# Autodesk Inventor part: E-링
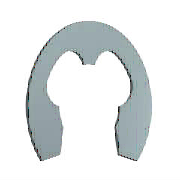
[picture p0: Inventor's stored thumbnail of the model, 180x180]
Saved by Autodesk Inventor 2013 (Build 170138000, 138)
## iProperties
IsCustomPart: 1
Created: 2012-02
Part Number: E-링
Material: 강철, 연강
Description: 일반용 테이퍼 및 줄어든 횡단면 리테이닝 링 - E-링 외부 시리즈 3CM1 리테이닝 링
Document SubType Name: Modeling
Standard: ANSI B27.7
Designer: mduedu
Standard Revision: 1999
Standards Organization: ANSI
Language: ko-KR
Size Designation: 5
Categories: <MemberInstance><Categories><Category DisplayName="샤프트 부품" InternalName="7f7aeb1f-a693-4053-b835-cee3144e0d98" Mnemonic="SHFT"><Category DisplayName="써클립" Inter
Density: 7.86 g/cm^3
Mass: 0.124029 g
Surface Area: 0.760929 cm^2
Volume: 0.0157798 cm^3
Author: mduedu
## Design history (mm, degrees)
sketch "스케치1"
  geometry: L1 (-0.39, 0.024)-(0, 0.024) reference; L2 (-3.206, 0)-(3.486, 0) reference; L3 (-1.787, -3.256)-(1.787, -3.256); L4 (0, 1.949)-(0, -3.479) reference; L5 (-2.34, -1.696)-(-1.958, -1.696); L6 (-0.39, -0.136)-(-0.39, 0.242); L7 (0, 1.774)-(2.53, 1.774); L8 (-1.787, -3.256)-(-2.367, -4.889); L9 (0, -0.526)-(-1.278, -0.526); L10 (1.787, -3.256)-(2.367, -4.889); L11 (2.34, -1.696)-(1.958, -1.696); L12 (0.39, -0.136)-(0.39, 0.242); C1 r 2.5 at (0, -2.476); A1 r 1.95 centre (0, -2.476) between (-1.847, -1.851) and (-1.787, -3.256); A2 r 0.39 centre (0, -0.136) between (-0.39, -0.136) and (0.39, -0.136); A3 r 4.25 centre (0, -2.476) between (3.384, -5.047) and (-3.384, -5.047); A4 r 3.12 centre (0, -2.476) between (-0.78, 0.545) and (-2.753, -1.008); A5 r 0.312 centre (-0.702, 0.242) between (-0.39, 0.242) and (-0.78, 0.545); A6 r 0.468 centre (-2.34, -1.228) between (-2.753, -1.008) and (-2.34, -1.696); A7 r 0.117 centre (-1.958, -1.813) between (-1.847, -1.851) and (-1.958, -1.696); A8 r 0.585 centre (-2.919, -4.693) between (-3.384, -5.047) and (-2.367, -4.889); A9 r 0.585 centre (2.919, -4.693) between (2.367, -4.889) and (3.384, -5.047); A10 r 1.95 centre (0, -2.476) between (1.787, -3.256) and (1.847, -1.851); A11 r 0.117 centre (1.958, -1.813) between (1.958, -1.696) and (1.847, -1.851); A12 r 0.468 centre (2.34, -1.228) between (2.34, -1.696) and (2.753, -1.008); A13 r 3.12 centre (0, -2.476) between (2.753, -1.008) and (0.78, 0.545); A14 r 0.312 centre (0.702, 0.242) between (0.78, 0.545) and (0.39, 0.242); 1 further point
  constraints: 30 point on circle, 20 end point, 15 centre point, 13 symmetric about line, 12 tangent, 8 point on line, 4 parallel, 2 coincident, 2 horizontal, 1 concentric, 1 perpendicular, 1 vertical alignment, 9 other
  dimensions: "d0" = 5 diameter of C1 (= WD); "d3" = 0.78 distance from line of A1.centre L3 (= 0.2 x ND); "d4" = 0.39 radius of A2 (= 0.1 x ND); "d5" = 8.5 diameter of A3 (= SD2); "d8" = 3.12 radius of A4 (= 0.8 x ND); "d9" = 0.78 distance from line of A1.centre L5 (= 0.2 x ND); "d10" = 0.312 radius of A5 (= 0.08 x ND); "d11" = 0.468 radius of A6 (= 0.12 x ND); "d12" = 0.117 radius of A7 (= 0.03 x ND); "d13" = 0.585 radius of A8 (= 0.15 x ND); "d14" = 1.95 distance from line of A1.centre L9 (= 0.5 x ND); "d15" = 1.95 radius of A1 (= 0.5 x ND)
extrude "본체" new body sketch "스케치1" distance "d16" = 0.6 (= SD); taper "d17" = 0 deg
workaxis "Work Axis1"
workaxis "Work Axis2"
workplane "Work Plane1"
body "Solid1"
other parameters: "ND" = 3.9 [user parameter; used in 14 equation terms], "SD" = 0.6 [user parameter; used in 1 equation term], "WD" = 5 (= WDMIN) [user parameter; used in 1 equation term], "d1" = 6.24 (= 1.6 x ND), "d2" = 3.9 (= ND), "SD2" = 8.5 [user parameter; used in 1 equation term], "d6" = 3.9 (= ND), "d7" = 0.585 (= 0.15 x ND), "d18" = 0, "d19" = 0, "d27" = 0, "d28" = 0, "WDMIN" = 5 [user parameter; used in 1 equation term], "SNB" = 0.7 [user parameter], "WDMAX" = 6 [user parameter], "BUBRMI" = 1.1 [user parameter]
